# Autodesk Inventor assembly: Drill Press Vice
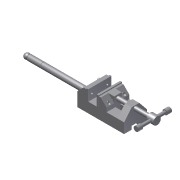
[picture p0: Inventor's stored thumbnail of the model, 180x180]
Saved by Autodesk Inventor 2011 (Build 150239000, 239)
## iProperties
Shininess: 64.0
Length Units: 11269
Angle Units: 11279
Time Units: 11290
Mass Units: 11283
Length Display Precision: 3
Angle Display Precision: 2
Created: 2002-02
Part Number: Drill Press Vice
Document SubType Name: Assembly
Designer: ***
Density: 0.0
Volumn: 0.0
Area: 0.0
PropertySet Name: Model Information
Control State: 0
Master: False
Checked Out: False
Author: ***
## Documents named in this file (9)
- C:\Users\CADSoft\Desktop\inventor\c13-inv-2010-prt\c13\fig-13-5 to 13-8\Drill Press Vice.iam
- C:\Users\CADSoft\Desktop\inventor\c13-inv-2010-prt\c13\fig-13-5 to 13-8\Base.ipt
- C:\Users\CADSoft\Desktop\inventor\c13-inv-2010-prt\c13\fig-13-5 to 13-8\Movable Jaw.ipt
- C:\Users\CADSoft\Desktop\inventor\c13-inv-2010-prt\c13\fig-13-5 to 13-8\Jaw Face.ipt
- C:\Users\CADSoft\Desktop\inventor\c13-inv-2010-prt\c13\fig-13-5 to 13-8\Clamp Screw.ipt
- C:\Users\CADSoft\Desktop\inventor\c13-inv-2010-prt\c13\fig-13-5 to 13-8\Clamp Screw Handle.ipt
- C:\Users\CADSoft\Desktop\inventor\c13-inv-2010-prt\c13\fig-13-5 to 13-8\Handle Stop.ipt
- C:\Users\CADSoft\Desktop\inventor\c13-inv-2010-prt\c13\fig-13-5 to 13-8\Cap Screw.ipt
- C:\Users\CADSoft\Desktop\inventor\c13-inv-2010-prt\c13\fig-13-5 to 13-8\Safety Handle.ipt
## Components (13 placed, 8 different names)
1. Base:1 — Insert:1, Insert:2, Insert:3, Angle:1, Angle:3, Insert:10, Insert:11, Insert:12
2. Movable Jaw:1 — Insert:1, Insert:2, Insert:4, Angle:2, Insert:5, Insert:8, Insert:9
3. Jaw Face:1 — Insert:4, Angle:2
4. Jaw Face:2 — Insert:3, Angle:1
5. Clamp Screw:1 — Insert:5, Angle:3, Mate:1, Mate:2
6. Clamp Screw Handle:1 — Mate:1, Mate:2, Insert:6, Insert:7
7. Handle Stop:1 — Insert:6
8. Handle Stop:2 — Insert:7
9. Cap Screw:1 — Insert:9
10. Cap Screw:2 — Insert:8
11. Cap Screw:4 — Insert:10
12. Cap Screw:5 — Insert:11
13. Safety Handle:1 — Insert:12
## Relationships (17: Insert 12, Angle 3, Mate 2)
- Insert:1: Base:1 ↔ Movable Jaw:1
- Insert:2: Base:1 ↔ Movable Jaw:1
- Insert:3: Base:1 ↔ Jaw Face:2
- Angle:1: Base:1 ↔ Jaw Face:2
- Insert:4: Movable Jaw:1 ↔ Jaw Face:1
- Angle:2: Movable Jaw:1 ↔ Jaw Face:1
- Insert:5: Movable Jaw:1 ↔ Clamp Screw:1
- Angle:3: Base:1 ↔ Clamp Screw:1
- Mate:1: Clamp Screw:1 ↔ Clamp Screw Handle:1
- Mate:2: Clamp Screw:1 ↔ Clamp Screw Handle:1
- Insert:6: Clamp Screw Handle:1 ↔ Handle Stop:1
- Insert:7: Clamp Screw Handle:1 ↔ Handle Stop:2
- Insert:8: Movable Jaw:1 ↔ Cap Screw:2
- Insert:9: Movable Jaw:1 ↔ Cap Screw:1
- Insert:10: Base:1 ↔ Cap Screw:4
- Insert:11: Base:1 ↔ Cap Screw:5
- Insert:12: Base:1 ↔ Safety Handle:1
